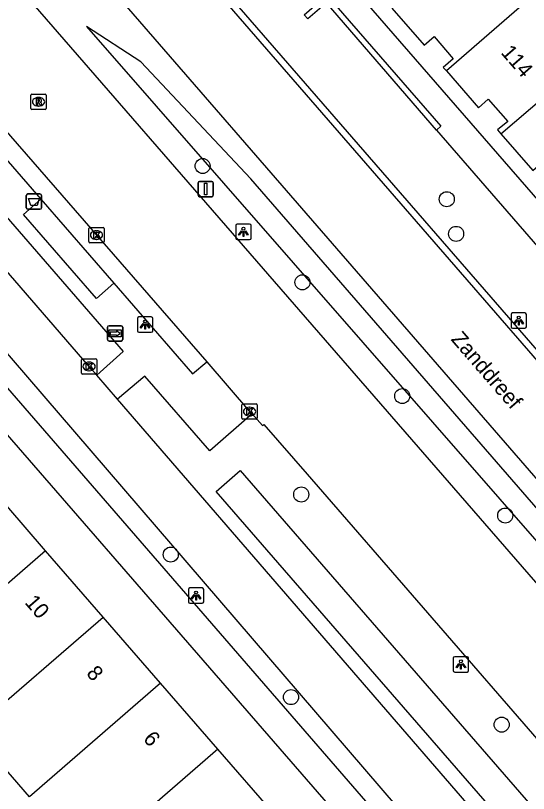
# Model space of a CAD drawing. Extents: x 155888 to 156864, y 383882 to 384671.
# Drawn here: x 156391.7 to 156425.1, y 384143.5 to 384194.1 of the extents above; entities that cross this region are included whole.
import ezdxf

# ---------------------------------------------------------------- set-up
doc = ezdxf.new("R2010")
doc.units = 0
for name, color, linetype in [('IMGEO_Afvalbak', 7, 'Continuous'), ('IMGEO_Boom', 7, 'Continuous'), ('IMGEO_Fietspad_gesloten', 7, 'Continuous'), ('IMGEO_Greppel_droge_sloot', 7, 'Continuous'), ('IMGEO_Kolk', 7, 'Continuous'), ('IMGEO_Lichtpunt', 7, 'Continuous'), ('IMGEO_Muur', 7, 'Continuous'), ('IMGEO_Openbare_ruimte_label', 7, 'Continuous'), ('IMGEO_OVBaan_gesloten', 7, 'Continuous'), ('IMGEO_Pand', 7, 'Continuous'), ('IMGEO_Pand_nummerreeks', 7, 'Continuous'), ('IMGEO_Rijbaan_lokaal_gesloten', 7, 'Continuous'), ('IMGEO_Rijbaan_lokaal_open', 7, 'Continuous'), ('IMGEO_Rioolput', 7, 'Continuous'), ('IMGEO_Verkeersbordpaal', 7, 'Continuous'), ('IMGEO_Voetpad_open', 7, 'Continuous'), ('IMGEO_Wegwijzer', 7, 'Continuous')]:
    doc.layers.add(name, color=color, linetype=linetype)

msp = doc.modelspace()

# ---------------------------------------------------------------- linework, layer by layer
at = {"layer": 'IMGEO_Afvalbak'}
for p, q in [((156392.387, 384181.57), (156392.387, 384182.37)), ((156392.387, 384182.37), (156392.387, 384181.57)), ((156392.487, 384182.47), (156393.277, 384182.47)), ((156393.277, 384182.47), (156392.487, 384182.47)), ((156393.377, 384182.37), (156393.377, 384181.57)), ((156393.377, 384181.57), (156393.377, 384182.37)), ((156393.277, 384181.47), (156392.487, 384181.47)), ((156392.487, 384181.47), (156393.277, 384181.47))]:
    msp.add_line(p, q, dxfattribs=at)
msp.add_lwpolyline([(156392.53, 384182.184), (156393.234, 384182.184), (156393.085, 384181.714), (156392.679, 384181.714), (156392.53, 384182.184)], dxfattribs=at)
for centre, start, end in [((156392.487, 384182.37), 90, 180), ((156392.487, 384182.37), 90, 180), ((156393.277, 384182.37), 0, 90), ((156393.277, 384182.37), 360, 90), ((156392.487, 384181.57), 180, 270), ((156392.487, 384181.57), 180, 270), ((156393.277, 384181.57), 270, 0), ((156393.277, 384181.57), 270, 0)]:
    msp.add_arc(centre, 0.1, start, end, dxfattribs=at)
at = {"layer": 'IMGEO_Boom'}
for centre in [(156403.858, 384184.289), (156419.74, 384182.126), (156420.35, 384179.874), (156410.353, 384176.72), (156416.842, 384169.32), (156410.273, 384162.913), (156423.542, 384161.544), (156401.786, 384159.003), (156409.607, 384149.727), (156423.312, 384147.937)]:
    msp.add_circle(centre, 0.489, dxfattribs=at)
at = {"layer": 'IMGEO_Fietspad_gesloten'}
for points in [[(156396.966, 384170.684), (156396.472, 384171.244), (156383.046, 384186.749), (156379.528, 384190.847)], [(156376.188, 384189.315), (156391.408, 384171.79), (156419.571, 384139)], [(156398.32, 384169.108), (156396.966, 384170.684)], [(156508.758, 384042.359), (156507.724, 384043.553), (156500, 384052.421), (156466.101, 384091.342), (156424.652, 384138.668), (156398.32, 384169.108)]]:
    msp.add_lwpolyline(points, dxfattribs=at)
at = {"layer": 'IMGEO_Greppel_droge_sloot'}
for points in [[(156519.582, 384053.811), (156500, 384076.291), (156482.527, 384096.349), (156446.804, 384137.574), (156406.998, 384183.444), (156399.832, 384191.076), (156396.295, 384193.376), (156445.697, 384136.86), (156481.572, 384095.447), (156500, 384074.342), (156518.628, 384053.007)], [(156465.542, 384096.235), (156466.952, 384094.195), (156466.196, 384093.465), (156464.825, 384093.911), (156404.729, 384163.106), (156406.31, 384164.479), (156465.542, 384096.235)]]:
    msp.add_lwpolyline(points, dxfattribs=at)
at = {"layer": 'IMGEO_Kolk'}
for p, q in [((156396.454, 384179.366), (156396.454, 384180.218)), ((156396.529, 384180.292), (156397.381, 384180.292)), ((156396.942, 384180.072), (156396.967, 384180.072)), ((156397.455, 384180.218), (156397.455, 384179.366)), ((156396.965, 384179.512), (156396.94, 384179.512)), ((156397.381, 384179.292), (156396.529, 384179.292)), ((156396.047, 384171.745), (156396.899, 384171.745)), ((156395.972, 384170.819), (156395.972, 384171.671)), ((156396.46, 384171.525), (156396.485, 384171.525)), ((156396.973, 384171.671), (156396.973, 384170.819)), ((156396.899, 384170.745), (156396.047, 384170.745)), ((156396.483, 384170.965), (156396.458, 384170.965)), ((156406.409, 384167.886), (156406.409, 384168.738)), ((156406.484, 384168.812), (156407.336, 384168.812)), ((156407.41, 384168.738), (156407.41, 384167.886)), ((156406.897, 384168.592), (156406.922, 384168.592)), ((156407.336, 384167.812), (156406.484, 384167.812)), ((156406.92, 384168.032), (156406.895, 384168.032))]:
    msp.add_line(p, q, dxfattribs=at)
for points in [[(156396.454, 384179.366), (156396.454, 384180.218)], [(156396.529, 384180.292), (156397.381, 384180.292)], [(156396.775, 384179.992), (156396.898, 384179.992), (156396.898, 384179.841), (156397.028, 384179.992), (156397.192, 384179.992), (156397.046, 384179.841), (156397.199, 384179.592), (156397.047, 384179.592), (156396.962, 384179.756), (156396.898, 384179.689), (156396.898, 384179.592), (156396.775, 384179.592), (156396.775, 384179.992)], [(156397.455, 384180.218), (156397.455, 384179.366)], [(156397.381, 384179.292), (156396.529, 384179.292)], [(156396.047, 384171.745), (156396.899, 384171.745)], [(156395.972, 384170.819), (156395.972, 384171.671)], [(156396.293, 384171.445), (156396.416, 384171.445), (156396.416, 384171.294), (156396.546, 384171.445), (156396.71, 384171.445), (156396.564, 384171.294), (156396.717, 384171.045), (156396.565, 384171.045), (156396.48, 384171.209), (156396.416, 384171.142), (156396.416, 384171.045), (156396.293, 384171.045), (156396.293, 384171.445)], [(156396.973, 384171.671), (156396.973, 384170.819)], [(156396.899, 384170.745), (156396.047, 384170.745)], [(156406.409, 384167.886), (156406.409, 384168.738)], [(156406.484, 384168.812), (156407.336, 384168.812)], [(156407.41, 384168.738), (156407.41, 384167.886)], [(156406.73, 384168.512), (156406.853, 384168.512), (156406.853, 384168.361), (156406.983, 384168.512), (156407.147, 384168.512), (156407.001, 384168.361), (156407.154, 384168.112), (156407.002, 384168.112), (156406.917, 384168.276), (156406.853, 384168.209), (156406.853, 384168.112), (156406.73, 384168.112), (156406.73, 384168.512)], [(156407.336, 384167.812), (156406.484, 384167.812)]]:
    msp.add_lwpolyline(points, dxfattribs=at)
for centre, start, end in [((156396.531, 384180.216), 91.552, 178.448), ((156396.531, 384180.216), 91.552, 178.448), ((156397.379, 384180.216), 1.552, 88.448), ((156397.379, 384180.216), 1.552, 88.448), ((156396.531, 384179.368), 181.552, 268.448), ((156396.531, 384179.368), 181.552, 268.448), ((156397.379, 384179.368), 271.552, 358.448), ((156397.379, 384179.368), 271.552, 358.448), ((156396.049, 384171.669), 91.552, 178.448), ((156396.049, 384171.669), 91.552, 178.448), ((156396.897, 384171.669), 1.552, 88.448), ((156396.897, 384171.669), 1.552, 88.448), ((156396.049, 384170.821), 181.552, 268.448), ((156396.049, 384170.821), 181.552, 268.448), ((156396.897, 384170.821), 271.552, 358.448), ((156396.897, 384170.821), 271.552, 358.448), ((156406.486, 384168.736), 91.552, 178.448), ((156406.486, 384168.736), 91.552, 178.448), ((156407.334, 384168.736), 1.552, 88.448), ((156407.334, 384168.736), 1.552, 88.448), ((156406.486, 384167.888), 181.552, 268.448), ((156406.486, 384167.888), 181.552, 268.448), ((156407.334, 384167.888), 271.552, 358.448), ((156407.334, 384167.888), 271.552, 358.448)]:
    msp.add_arc(centre, 0.0765, start, end, dxfattribs=at)
for centre, major_axis, ratio, start_param, end_param in [((156396.941, 384179.792), (-0.387, 0.002), 0.722429, 4.712389, 7.853982), ((156396.966, 384179.792), (-0.39, 0.002), 0.717154, 1.570796, 4.712389), ((156396.459, 384171.245), (-0.387, 0.002), 0.722429, 4.712389, 7.853982), ((156396.484, 384171.245), (-0.39, 0.002), 0.717154, 1.570796, 4.712389), ((156406.896, 384168.312), (-0.387, 0.002), 0.722429, 4.712389, 7.853982), ((156406.921, 384168.312), (-0.39, 0.002), 0.717154, 1.570796, 4.712389)]:
    msp.add_ellipse(centre, major_axis=major_axis, ratio=ratio, start_param=start_param, end_param=end_param, dxfattribs=at)
at = {"layer": 'IMGEO_Lichtpunt'}
for p, q in [((156406.015, 384180.409), (156406.015, 384179.602)), ((156406.015, 384180.409), (156406.015, 384179.602)), ((156406.917, 384180.504), (156406.109, 384180.504)), ((156406.917, 384180.504), (156406.109, 384180.504)), ((156407.011, 384179.602), (156407.011, 384180.409)), ((156407.011, 384179.602), (156407.011, 384180.409)), ((156406.109, 384179.508), (156406.917, 384179.508)), ((156406.109, 384179.508), (156406.917, 384179.508)), ((156399.619, 384174.371), (156399.619, 384173.564)), ((156399.619, 384174.371), (156399.619, 384173.564)), ((156400.521, 384174.466), (156399.713, 384174.466)), ((156400.521, 384174.466), (156399.713, 384174.466)), ((156400.615, 384173.564), (156400.615, 384174.371)), ((156400.615, 384173.564), (156400.615, 384174.371)), ((156423.924, 384174.63), (156423.924, 384173.823)), ((156423.924, 384174.63), (156423.924, 384173.823)), ((156424.826, 384174.725), (156424.018, 384174.725)), ((156424.826, 384174.725), (156424.018, 384174.725)), ((156424.92, 384173.823), (156424.92, 384174.63)), ((156424.92, 384173.823), (156424.92, 384174.63)), ((156399.713, 384173.47), (156400.521, 384173.47)), ((156399.713, 384173.47), (156400.521, 384173.47)), ((156424.018, 384173.729), (156424.826, 384173.729)), ((156424.018, 384173.729), (156424.826, 384173.729)), ((156402.934, 384156.736), (156402.934, 384155.929)), ((156402.934, 384156.736), (156402.934, 384155.929)), ((156403.836, 384156.831), (156403.028, 384156.831)), ((156403.836, 384156.831), (156403.028, 384156.831)), ((156403.93, 384155.929), (156403.93, 384156.736)), ((156403.93, 384155.929), (156403.93, 384156.736)), ((156403.028, 384155.835), (156403.836, 384155.835)), ((156403.028, 384155.835), (156403.836, 384155.835)), ((156420.161, 384152.26), (156420.161, 384151.453)), ((156420.161, 384152.26), (156420.161, 384151.453)), ((156421.063, 384152.355), (156420.255, 384152.355)), ((156421.063, 384152.355), (156420.255, 384152.355)), ((156421.157, 384151.453), (156421.157, 384152.26)), ((156421.157, 384151.453), (156421.157, 384152.26)), ((156420.255, 384151.359), (156421.063, 384151.359)), ((156420.255, 384151.359), (156421.063, 384151.359))]:
    msp.add_line(p, q, dxfattribs=at)
for points in [[(156406.389, 384180.073), (156406.428, 384180.045), (156406.24, 384179.783), (156406.202, 384179.81), (156406.389, 384180.073)], [(156406.491, 384180.025), (156406.538, 384180.025), (156406.538, 384179.703), (156406.491, 384179.703), (156406.491, 384180.025)], [(156406.601, 384180.045), (156406.639, 384180.072), (156406.826, 384179.81), (156406.787, 384179.782), (156406.601, 384180.045)], [(156424.298, 384174.294), (156424.337, 384174.266), (156424.149, 384174.004), (156424.111, 384174.031), (156424.298, 384174.294)], [(156424.4, 384174.246), (156424.447, 384174.246), (156424.447, 384173.924), (156424.4, 384173.924), (156424.4, 384174.246)], [(156424.51, 384174.266), (156424.548, 384174.293), (156424.735, 384174.031), (156424.696, 384174.003), (156424.51, 384174.266)], [(156399.993, 384174.035), (156400.032, 384174.007), (156399.844, 384173.745), (156399.806, 384173.772), (156399.993, 384174.035)], [(156400.095, 384173.987), (156400.142, 384173.987), (156400.142, 384173.665), (156400.095, 384173.665), (156400.095, 384173.987)], [(156400.205, 384174.007), (156400.243, 384174.034), (156400.43, 384173.772), (156400.391, 384173.744), (156400.205, 384174.007)], [(156403.308, 384156.4), (156403.347, 384156.372), (156403.159, 384156.11), (156403.121, 384156.137), (156403.308, 384156.4)], [(156403.41, 384156.352), (156403.457, 384156.352), (156403.457, 384156.03), (156403.41, 384156.03), (156403.41, 384156.352)], [(156403.52, 384156.372), (156403.558, 384156.399), (156403.745, 384156.137), (156403.706, 384156.109), (156403.52, 384156.372)], [(156420.535, 384151.924), (156420.574, 384151.896), (156420.386, 384151.634), (156420.348, 384151.661), (156420.535, 384151.924)], [(156420.637, 384151.876), (156420.684, 384151.876), (156420.684, 384151.554), (156420.637, 384151.554), (156420.637, 384151.876)], [(156420.747, 384151.896), (156420.785, 384151.923), (156420.972, 384151.661), (156420.933, 384151.633), (156420.747, 384151.896)]]:
    msp.add_lwpolyline(points, dxfattribs=at)
for centre in [(156406.514, 384180.207), (156400.118, 384174.169), (156424.423, 384174.428), (156403.433, 384156.534), (156420.66, 384152.058)]:
    msp.add_circle(centre, 0.0994, dxfattribs=at)
for centre, start, end in [((156406.109, 384180.409), 90, 180), ((156406.109, 384180.409), 90, 180), ((156406.917, 384180.409), 0, 90), ((156406.917, 384180.409), 0, 90), ((156406.109, 384179.602), 180, 270), ((156406.109, 384179.602), 180, 270), ((156406.917, 384179.602), 270, 0), ((156406.917, 384179.602), 270, 360), ((156399.713, 384174.371), 90, 180), ((156399.713, 384174.371), 90, 180), ((156400.521, 384174.371), 0, 90), ((156400.521, 384174.371), 0, 90), ((156424.018, 384174.63), 90, 180), ((156424.018, 384174.63), 90, 180), ((156424.826, 384174.63), 0, 90), ((156424.826, 384174.63), 0, 90), ((156424.018, 384173.823), 180, 270), ((156424.018, 384173.823), 180, 270), ((156424.826, 384173.823), 270, 0), ((156424.826, 384173.823), 270, 360), ((156399.713, 384173.564), 180, 270), ((156399.713, 384173.564), 180, 270), ((156400.521, 384173.564), 270, 0), ((156400.521, 384173.564), 270, 360), ((156403.028, 384156.736), 90, 180), ((156403.028, 384156.736), 90, 180), ((156403.836, 384156.736), 0, 90), ((156403.836, 384156.736), 0, 90), ((156403.028, 384155.929), 180, 270), ((156403.028, 384155.929), 180, 270), ((156403.836, 384155.929), 270, 0), ((156403.836, 384155.929), 270, 360), ((156420.255, 384152.26), 90, 180), ((156420.255, 384152.26), 90, 180), ((156421.063, 384152.26), 0, 90), ((156421.063, 384152.26), 0, 90), ((156420.255, 384151.453), 180, 270), ((156420.255, 384151.453), 180, 270), ((156421.063, 384151.453), 270, 0), ((156421.063, 384151.453), 270, 360)]:
    msp.add_arc(centre, 0.0946, start, end, dxfattribs=at)
at = {"layer": 'IMGEO_Muur'}
for points in [[(156419.063, 384186.621), (156411.914, 384194.897), (156410.699, 384193.856), (156410.457, 384194.135), (156411.932, 384195.424)], [(156411.932, 384195.424), (156419.35, 384186.891), (156419.063, 384186.621)]]:
    msp.add_lwpolyline(points, dxfattribs=at)
at = {"layer": 'IMGEO_OVBaan_gesloten'}
for points in [[(156517.145, 384051.764), (156500, 384071.498), (156389.213, 384199.015)], [(156385.683, 384192.735), (156404.132, 384171.551)], [(156404.132, 384171.551), (156406.911, 384168.313), (156407.083, 384168.169)], [(156407.083, 384168.169), (156407.746, 384167.396), (156407.842, 384167.479), (156410.66, 384164.227), (156441.975, 384128.147), (156500, 384061.368), (156513.218, 384046.155)]]:
    msp.add_lwpolyline(points, dxfattribs=at)
at = {"layer": 'IMGEO_Pand'}
for points in [[(156430.655, 384199.988), (156419.712, 384190.473)], [(156423.259, 384186.391), (156433.493, 384195.149), (156434.007, 384195.597)], [(156416.175, 384194.553), (156418.263, 384192.153), (156418.912, 384192.718), (156420.149, 384191.267), (156419.509, 384190.706), (156419.712, 384190.473)], [(156419.712, 384190.473), (156421.794, 384188.083), (156422.443, 384188.648), (156423.704, 384187.19), (156423.047, 384186.634), (156423.259, 384186.391)], [(156423.259, 384186.391), (156425.338, 384184.005), (156425.986, 384184.57), (156427.251, 384183.119), (156426.59, 384182.558), (156426.801, 384182.316)], [(156393.64, 384159.255), (156389.905, 384163.561)], [(156393.64, 384159.255), (156385.117, 384151.853)], [(156397.387, 384154.938), (156393.64, 384159.255)], [(156388.853, 384147.547), (156397.387, 384154.938)], [(156401.121, 384150.635), (156397.387, 384154.938)], [(156401.121, 384150.635), (156392.587, 384143.245)], [(156404.854, 384146.332), (156401.121, 384150.635)], [(156392.587, 384143.245), (156388.853, 384147.547)], [(156404.854, 384146.332), (156396.322, 384138.942)], [(156408.584, 384142.034), (156408.463, 384142.173), (156404.854, 384146.332)]]:
    msp.add_lwpolyline(points, dxfattribs=at)
at = {"layer": 'IMGEO_Rijbaan_lokaal_gesloten'}
for points in [[(156395.631, 384206.125), (156395.653, 384206.088), (156395.745, 384205.951), (156395.847, 384205.822), (156395.961, 384205.703), (156396.428, 384205.193), (156399.273, 384201.968), (156437.383, 384158.067), (156443.7, 384150.805), (156476.876, 384112.6), (156481.951, 384106.723), (156483.127, 384105.407), (156500, 384085.986), (156516.29, 384067.237), (156517.607, 384065.738), (156518.453, 384064.739), (156519.101, 384063.991), (156519.163, 384063.918), (156519.227, 384063.847), (156519.291, 384063.776)], [(156527.288, 384046.812), (156520.535, 384054.614), (156504.298, 384073.374), (156500, 384078.319), (156478.069, 384103.539), (156435.386, 384152.651), (156395.779, 384198.307), (156392.544, 384201.972)]]:
    msp.add_lwpolyline(points, dxfattribs=at)
at = {"layer": 'IMGEO_Rijbaan_lokaal_open'}
msp.add_lwpolyline([(156437.73, 384158.369), (156399.619, 384202.271), (156396.759, 384205.513)], dxfattribs=at)
at = {"layer": 'IMGEO_Rioolput'}
for p, q in [((156392.758, 384188.967), (156393.61, 384188.967)), ((156392.683, 384188.041), (156392.683, 384188.893)), ((156393.171, 384188.747), (156393.196, 384188.747)), ((156393.684, 384188.893), (156393.684, 384188.041)), ((156393.61, 384187.967), (156392.758, 384187.967)), ((156393.194, 384188.187), (156393.169, 384188.187))]:
    msp.add_line(p, q, dxfattribs=at)
for points in [[(156392.758, 384188.967), (156393.61, 384188.967)], [(156392.683, 384188.041), (156392.683, 384188.893)], [(156393.272, 384188.665), (156393.02, 384188.667), (156393.02, 384188.267)], [(156393.02, 384188.267), (156393.144, 384188.267), (156393.144, 384188.429), (156393.155, 384188.429)], [(156393.198, 384188.586), (156393.144, 384188.586), (156393.144, 384188.505)], [(156393.144, 384188.505), (156393.196, 384188.505)], [(156393.684, 384188.893), (156393.684, 384188.041)], [(156393.61, 384187.967), (156392.758, 384187.967)], [(156393.202, 384188.4), (156393.273, 384188.267), (156393.413, 384188.267), (156393.348, 384188.393)]]:
    msp.add_lwpolyline(points, dxfattribs=at)
for centre, radius, start, end in [((156392.76, 384188.891), 0.0765, 91.552, 178.448), ((156392.76, 384188.891), 0.0765, 91.552, 178.448), ((156393.608, 384188.891), 0.0765, 1.552, 88.448), ((156393.608, 384188.891), 0.0765, 1.552, 88.448), ((156393.154, 384188.376), 0.0533, 26.0293, 88.6989), ((156393.18, 384188.694), 0.19, 274.7715, 282.9687), ((156393.204, 384188.49), 0.0964, 77.0061, 93.1865), ((156393.218, 384188.547), 0.0378, 276.6634, 79.6772), ((156393.271, 384188.555), 0.109, 350.3612, 89.416), ((156393.269, 384188.555), 0.112, 277.5842, 350.9817), ((156393.253, 384188.34), 0.108, 29.5134, 73.7905), ((156392.76, 384188.043), 0.0765, 181.552, 268.448), ((156392.76, 384188.043), 0.0765, 181.552, 268.448), ((156393.608, 384188.043), 0.0765, 271.552, 358.448), ((156393.608, 384188.043), 0.0765, 271.552, 358.448)]:
    msp.add_arc(centre, radius, start, end, dxfattribs=at)
for centre, major_axis, ratio, start_param, end_param in [((156393.17, 384188.467), (-0.387, 0.002), 0.722429, 4.712389, 7.853982), ((156393.195, 384188.467), (-0.39, 0.002), 0.717154, 1.570796, 4.712389)]:
    msp.add_ellipse(centre, major_axis=major_axis, ratio=ratio, start_param=start_param, end_param=end_param, dxfattribs=at)
at = {"layer": 'IMGEO_Verkeersbordpaal'}
for p, q in [((156403.565, 384182.39), (156403.565, 384183.19)), ((156403.565, 384183.19), (156403.565, 384182.39)), ((156403.665, 384183.29), (156404.455, 384183.29)), ((156404.455, 384183.29), (156403.665, 384183.29)), ((156404.555, 384183.19), (156404.555, 384182.39)), ((156404.555, 384182.39), (156404.555, 384183.19)), ((156404.455, 384182.29), (156403.665, 384182.29)), ((156403.665, 384182.29), (156404.455, 384182.29))]:
    msp.add_line(p, q, dxfattribs=at)
msp.add_lwpolyline([(156403.985, 384183.165), (156404.135, 384183.165), (156404.135, 384182.415), (156403.985, 384182.415), (156403.985, 384183.165)], dxfattribs=at)
for centre, start, end in [((156403.665, 384183.19), 90, 180), ((156403.665, 384183.19), 90, 180), ((156404.455, 384183.19), 0, 90), ((156404.455, 384183.19), 360, 90), ((156403.665, 384182.39), 180, 270), ((156403.665, 384182.39), 180, 270), ((156404.455, 384182.39), 270, 0), ((156404.455, 384182.39), 270, 0)]:
    msp.add_arc(centre, 0.1, start, end, dxfattribs=at)
at = {"layer": 'IMGEO_Voetpad_open'}
for points in [[(156443.915, 384161.094), (156408.135, 384202.27)], [(156385.683, 384192.735), (156384.802, 384191.938), (156393.336, 384182.121)], [(156381.202, 384192.382), (156398.69, 384172.225), (156396.966, 384170.684)], [(156419.063, 384186.621), (156442.384, 384159.766)], [(156398.084, 384176.658), (156396.955, 384175.676), (156392.204, 384181.137), (156393.336, 384182.121)], [(156393.336, 384182.121), (156398.084, 384176.658)], [(156419.983, 384136.598), (156381.718, 384180.744)], [(156380.825, 384178.663), (156414.166, 384140.264)], [(156398.084, 384176.658), (156403.21, 384170.762), (156404.132, 384171.551)], [(156407.083, 384168.169), (156404.338, 384165.752), (156400.091, 384170.612), (156398.32, 384169.108)]]:
    msp.add_lwpolyline(points, dxfattribs=at)
at = {"layer": 'IMGEO_Wegwijzer'}
for p, q in [((156397.67, 384172.997), (156397.67, 384173.797)), ((156397.67, 384173.797), (156397.67, 384172.997)), ((156397.77, 384173.897), (156398.56, 384173.897)), ((156398.56, 384173.897), (156397.77, 384173.897)), ((156398.66, 384173.797), (156398.66, 384172.997)), ((156398.66, 384172.997), (156398.66, 384173.797)), ((156398.56, 384172.897), (156397.77, 384172.897)), ((156397.77, 384172.897), (156398.56, 384172.897))]:
    msp.add_line(p, q, dxfattribs=at)
for points in [[(156397.771, 384173.629), (156398.559, 384173.629), (156398.559, 384173.165), (156397.771, 384173.165), (156397.771, 384173.629)], [(156397.836, 384173.481), (156397.836, 384173.397), (156397.836, 384173.313), (156398.247, 384173.313), (156398.247, 384173.23), (156398.494, 384173.397), (156398.247, 384173.564), (156398.247, 384173.481), (156397.836, 384173.481)]]:
    msp.add_lwpolyline(points, dxfattribs=at)
for centre, start, end in [((156397.77, 384173.797), 90, 180), ((156397.77, 384173.797), 90, 180), ((156398.56, 384173.797), 0, 90), ((156398.56, 384173.797), 360, 90), ((156397.77, 384172.997), 180, 270), ((156397.77, 384172.997), 180, 270), ((156398.56, 384172.997), 270, 0), ((156398.56, 384172.997), 270, 0)]:
    msp.add_arc(centre, 0.1, start, end, dxfattribs=at)

# ---------------------------------------------------------------- texts
at = {"layer": 'IMGEO_Openbare_ruimte_label'}
msp.add_text('Zanddreef', height=1, rotation=310.9433, dxfattribs=at).set_placement((156419.969, 384172.989))
at = {"layer": 'IMGEO_Pand_nummerreeks'}
for s, rotation, p in [('114', 310.9548, (156423.214, 384191.645)), ('10', 310.9488, (156392.243, 384155.861)), ('8', 310.9488, (156396.246, 384151.247)), ('6', 310.9488, (156399.944, 384146.985))]:
    msp.add_text(s, height=1, rotation=rotation, dxfattribs=at).set_placement(p)

doc.saveas('drawing.dxf')
